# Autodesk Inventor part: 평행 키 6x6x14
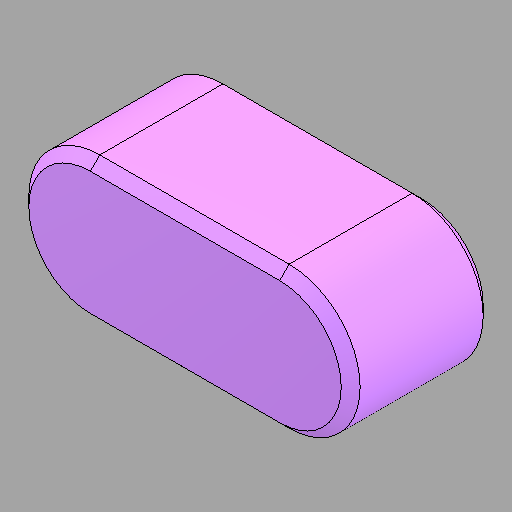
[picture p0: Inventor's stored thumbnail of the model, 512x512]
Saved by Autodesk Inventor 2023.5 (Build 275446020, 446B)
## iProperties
Created: 2025-07
Part Number: 평행 키 6x6x14
Material: 강철, 연강
Description: 키 및 해당 키홈
Document SubType Name: Modeling
Designer: 1강의실14
Density: 7.85 g/cm^3
Appearance: 기본값
Author: jhkim
Sending System: Autodesk Inventor 2026
Preprocessor: ST-DEVELOPER v20.1
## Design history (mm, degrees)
feature "Solid1"
node "솔리드1"
